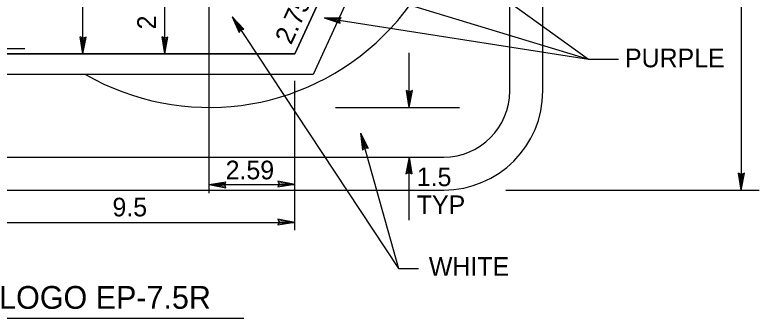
# Model space of a CAD drawing. Extents: x 10268197 to 10269179, y 2141503 to 2142677.
# Drawn here: x 10268668.41 to 10268696.57, y 2142131.77 to 2142143.23 of the extents above; entities that cross this region are included whole.
import ezdxf

# ---------------------------------------------------------------- set-up
doc = ezdxf.new("R2010")
doc.units = 0
for name, color, linetype in [('1', 7, 'Continuous'), ('21', 7, 'Continuous'), ('Default', 7, 'Continuous'), ('TextMisc', 7, 'Continuous'), ('TextShtNo', 7, 'Continuous')]:
    doc.layers.add(name, color=color, linetype=linetype)

msp = doc.modelspace()

# ---------------------------------------------------------------- linework, layer by layer
at = {"layer": '1'}
for p, q in [((10268680.189, 2142148.714), (10268690.11, 2142141.554)), ((10268675.962, 2142145.858), (10268690.11, 2142141.554)), ((10268680.112, 2142143.122), (10268690.11, 2142141.554)), ((10268690.11, 2142141.554), (10268691.243, 2142141.554))]:
    msp.add_line(p, q, dxfattribs=at)
at = {"layer": '21'}
msp.add_line((10268667.229, 2142131.765), (10268677.069, 2142131.765), dxfattribs=at)
at = {"layer": 'Default'}
for p, q in [((10268695.888, 2142161.607), (10268695.888, 2142136.607)), ((10268687.132, 2142140.357), (10268687.132, 2142157.857)), ((10268670.985, 2142141.757), (10268670.985, 2142156.491)), ((10268675.757, 2142136.494), (10268675.757, 2142149.107)), ((10268680.512, 2142145.04), (10268678.995, 2142141.757)), ((10268674.078, 2142141.757), (10268674.078, 2142144.212)), ((10268681.205, 2142144.263), (10268679.689, 2142140.981)), ((10268676.626, 2142143.155), (10268682.918, 2142133.64)), ((10268676.626, 2142143.155), (10268677.076, 2142142.69)), ((10268676.626, 2142143.155), (10268676.89, 2142142.564)), ((10268676.626, 2142143.155), (10268676.925, 2142142.618)), ((10268676.626, 2142143.155), (10268677.013, 2142142.678)), ((10268680.112, 2142143.122), (10268680.757, 2142143.135)), ((10268680.112, 2142143.122), (10268680.721, 2142142.913)), ((10268680.112, 2142143.122), (10268680.706, 2142142.975)), ((10268680.112, 2142143.122), (10268680.722, 2142143.081)), ((10268680.691, 2142143.031), (10268680.757, 2142143.135)), ((10268680.721, 2142142.913), (10268680.691, 2142143.031)), ((10268676.89, 2142142.564), (10268676.956, 2142142.668)), ((10268676.956, 2142142.668), (10268677.076, 2142142.69)), ((10268670.985, 2142141.757), (10268670.884, 2142142.397)), ((10268670.995, 2142142.346), (10268670.884, 2142142.397)), ((10268670.985, 2142141.757), (10268670.942, 2142142.37)), ((10268670.985, 2142141.757), (10268671.108, 2142142.393)), ((10268670.985, 2142141.757), (10268671.049, 2142142.369)), ((10268671.108, 2142142.393), (10268670.995, 2142142.346)), ((10268674.078, 2142141.757), (10268673.977, 2142142.397)), ((10268674.088, 2142142.346), (10268673.977, 2142142.397)), ((10268674.078, 2142141.757), (10268674.035, 2142142.37)), ((10268674.078, 2142141.757), (10268674.201, 2142142.393)), ((10268674.078, 2142141.757), (10268674.142, 2142142.369)), ((10268674.201, 2142142.393), (10268674.088, 2142142.346)), ((10268666.874, 2142141.959), (10268668.781, 2142141.959)), ((10268683.325, 2142139.732), (10268683.325, 2142141.794)), ((10268678.995, 2142141.757), (10268667.747, 2142141.757)), ((10268679.689, 2142140.981), (10268667.389, 2142140.981)), ((10268678.995, 2142135.093), (10268678.995, 2142140.739)), ((10268683.325, 2142139.732), (10268683.224, 2142140.371)), ((10268683.335, 2142140.321), (10268683.224, 2142140.371)), ((10268683.325, 2142139.732), (10268683.282, 2142140.345)), ((10268683.325, 2142139.732), (10268683.448, 2142140.368)), ((10268683.325, 2142139.732), (10268683.389, 2142140.344)), ((10268683.448, 2142140.368), (10268683.335, 2142140.321)), ((10268680.542, 2142139.732), (10268685.229, 2142139.732)), ((10268681.48, 2142138.764), (10268682.918, 2142133.64)), ((10268681.48, 2142138.763), (10268681.772, 2142138.186)), ((10268681.48, 2142138.763), (10268681.558, 2142138.121)), ((10268681.48, 2142138.763), (10268681.607, 2142138.162)), ((10268681.48, 2142138.763), (10268681.709, 2142138.193)), ((10268681.558, 2142138.121), (10268681.651, 2142138.2)), ((10268681.651, 2142138.2), (10268681.772, 2142138.186)), ((10268659.632, 2142137.857), (10268684.632, 2142137.857)), ((10268683.325, 2142137.857), (10268683.202, 2142137.221)), ((10268683.325, 2142137.857), (10268683.261, 2142137.246)), ((10268683.325, 2142135.464), (10268683.325, 2142137.857)), ((10268683.325, 2142137.857), (10268683.426, 2142137.218)), ((10268683.325, 2142137.857), (10268683.368, 2142137.245)), ((10268683.202, 2142137.221), (10268683.315, 2142137.268)), ((10268683.315, 2142137.268), (10268683.426, 2142137.218)), ((10268695.888, 2142136.607), (10268695.787, 2142137.247)), ((10268695.898, 2142137.196), (10268695.787, 2142137.247)), ((10268695.888, 2142136.607), (10268695.845, 2142137.22)), ((10268695.888, 2142136.607), (10268696.011, 2142137.243)), ((10268695.888, 2142136.607), (10268695.952, 2142137.219)), ((10268696.011, 2142137.243), (10268695.898, 2142137.196)), ((10268675.757, 2142136.821), (10268676.396, 2142136.922)), ((10268675.757, 2142136.821), (10268676.369, 2142136.864)), ((10268675.757, 2142136.821), (10268678.995, 2142136.821)), ((10268675.757, 2142136.821), (10268676.393, 2142136.698)), ((10268675.757, 2142136.821), (10268676.368, 2142136.757)), ((10268676.346, 2142136.811), (10268676.396, 2142136.922)), ((10268676.393, 2142136.698), (10268676.346, 2142136.811)), ((10268678.407, 2142136.831), (10268678.356, 2142136.72)), ((10268678.995, 2142136.821), (10268678.356, 2142136.72)), ((10268678.995, 2142136.821), (10268678.36, 2142136.944)), ((10268678.36, 2142136.944), (10268678.407, 2142136.831)), ((10268678.995, 2142136.821), (10268678.383, 2142136.778)), ((10268678.995, 2142136.821), (10268678.384, 2142136.885)), ((10268667.12, 2142135.383), (10268678.995, 2142135.383)), ((10268678.407, 2142135.393), (10268678.356, 2142135.282)), ((10268678.995, 2142135.383), (10268678.356, 2142135.282)), ((10268678.995, 2142135.383), (10268678.36, 2142135.506)), ((10268678.36, 2142135.506), (10268678.407, 2142135.393)), ((10268678.995, 2142135.383), (10268678.383, 2142135.34)), ((10268678.995, 2142135.383), (10268678.384, 2142135.447)), ((10268682.918, 2142133.64), (10268683.675, 2142133.64))]:
    msp.add_line(p, q, dxfattribs=at)
for centre, major_axis, start_param, end_param in [((10268675.757, 2142149.107), (0, 9.375), 2.619545, 5.22594), ((10268684.632, 2142140.357), (0, -2.5), 0, 1.570796)]:
    msp.add_ellipse(centre, major_axis=major_axis, ratio=0.999997, start_param=start_param, end_param=end_param, dxfattribs=at)
at = {"layer": 'TextMisc'}
for p, q in [((10268688.382, 2142140.357), (10268688.382, 2142157.857)), ((10268659.632, 2142136.607), (10268684.632, 2142136.607)), ((10268686.989, 2142136.607), (10268696.565, 2142136.607))]:
    msp.add_line(p, q, dxfattribs=at)
msp.add_ellipse((10268684.632, 2142140.357), major_axis=(0, -3.75), ratio=0.999998, start_param=0, end_param=1.570796, dxfattribs=at)
at = {"layer": 'TextShtNo'}
for p, q in [((10268678.995, 2142141.757), (10268680.153, 2142144.263)), ((10268681.205, 2142144.263), (10268679.689, 2142140.981)), ((10268667.747, 2142141.757), (10268678.995, 2142141.757)), ((10268679.689, 2142140.981), (10268667.389, 2142140.981))]:
    msp.add_line(p, q, dxfattribs=at)

# ---------------------------------------------------------------- texts
at = {"layer": '1'}
for s, height, rotation, p in [('2.75', 0.7047, 65.0602, (10268678.858, 2142142.072)), ('2', 0.705, 90, (10268673.744, 2142142.685))]:
    msp.add_text(s, height=height, rotation=rotation, dxfattribs=at).set_placement(p)
for s, height, p in [('PURPLE', 0.7047, (10268691.49, 2142141.251)), ('2.59', 0.7047, (10268676.383, 2142137.014)), ('1.5', 0.7047, (10268683.614, 2142136.755)), ('9.5', 0.7047, (10268672.101, 2142135.612)), ('TYP', 0.7047, (10268683.614, 2142135.698)), ('WHITE', 0.7047, (10268684.072, 2142133.367)), ('LOGO EP-7.5R', 0.8624, (10268667.814, 2142132.117))]:
    msp.add_text(s, height=height, dxfattribs=at).set_placement(p)

doc.saveas('drawing.dxf')
